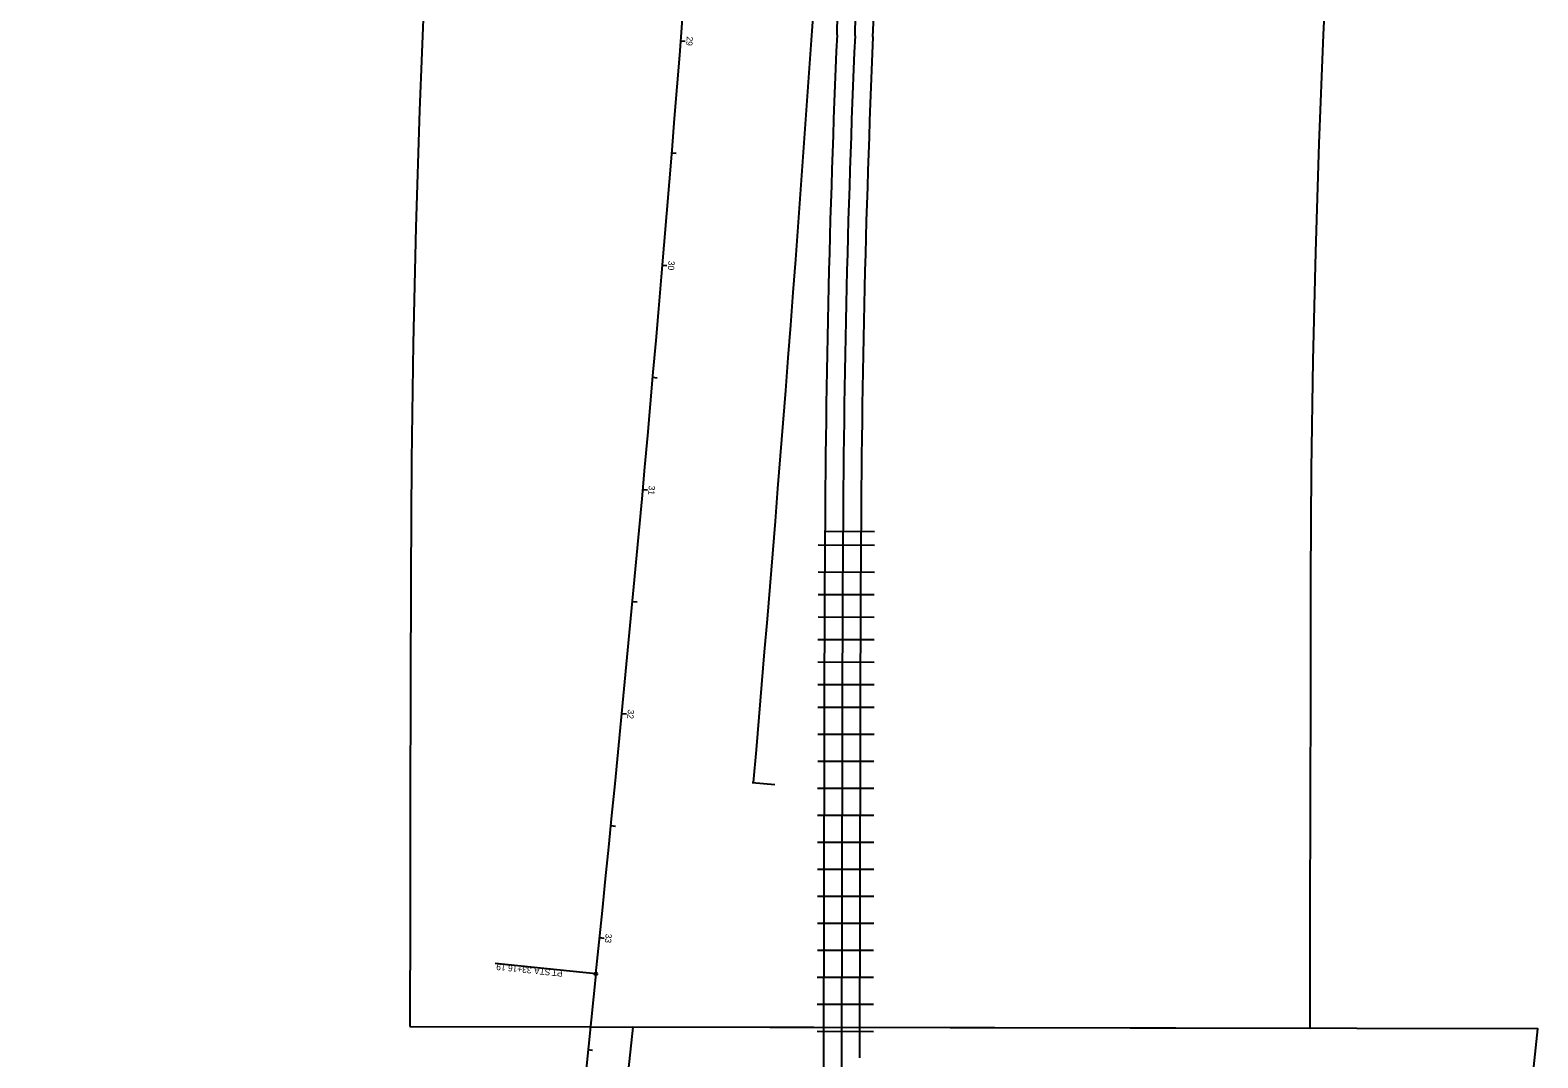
# Model space of a CAD drawing. Extents: x 172043 to 172847, y 249504 to 259737.
# Drawn here: x 172177 to 172847, y 256386 to 256843 of the extents above; entities that cross this region are included whole.
import ezdxf

# ---------------------------------------------------------------- set-up
doc = ezdxf.new("R2010")
doc.units = 0
for name, color, linetype in [('PM_X_Surveyed_Line', 7, 'Continuous'), ('PV_X_EOP', 7, 'Continuous'), ('PV_X_Shoulder', 7, 'Continuous'), ('RW_X_CL_100_Distances', 7, 'Continuous')]:
    doc.layers.add(name, color=color, linetype=linetype)

msp = doc.modelspace()

# ---------------------------------------------------------------- linework, layer by layer
at = {"layer": 'PM_X_Surveyed_Line'}
for p, q in [((172466.38, 256837.82), (172468.37, 256837.66)), ((172466.38, 256837.82), (172468.37, 256837.66)), ((172462.38, 256787.98), (172464.38, 256787.81)), ((172458.24, 256738.15), (172460.24, 256737.98)), ((172458.24, 256738.15), (172460.24, 256737.98)), ((172453.96, 256688.33), (172455.95, 256688.16)), ((172449.52, 256638.53), (172451.51, 256638.35)), ((172449.52, 256638.53), (172451.51, 256638.35)), ((172444.94, 256588.74), (172446.93, 256588.55)), ((172440.22, 256538.96), (172442.21, 256538.77)), ((172440.22, 256538.96), (172442.21, 256538.77)), ((172435.34, 256489.2), (172437.33, 256489)), ((172430.32, 256439.45), (172432.31, 256439.25)), ((172430.32, 256439.45), (172432.31, 256439.25)), ((172428.67, 256423.35), (172383.9, 256427.98)), ((172428.67, 256423.35), (172177.28, 253990.91)), ((172425.19, 256389.72), (172427.18, 256389.51))]:
    msp.add_line(p, q, dxfattribs=at)
msp.add_circle((172428.67, 256423.35), 0.6, dxfattribs=at)
msp.add_arc((155518.73, 258170.95), 17000, 354.099581, 0.195474, dxfattribs=at)
msp.add_arc((155518.73, 258170.95), 17000, 354.099581, 0.195474, dxfattribs=at)
at = {"layer": 'PV_X_EOP'}
msp.add_line((172545.97, 256386.02), (172546.38, 256601.68), dxfattribs=at)
for centre, radius, start, end in [((151025.86, 258352.49), 21551.92, 355.091243, 0.046603), ((178275.97, 256590.76), 5729.6, 177.510759, 179.890758)]:
    msp.add_arc(centre, radius, start, end, dxfattribs=at)
msp.add_open_spline([(172551.77, 256839.6), (172552.5, 256856.26), (172554.08, 256889.55), (172556.81, 256939.48), (172559.73, 256989.39), (172561.77, 257022.66), (172562.78, 257039.3)], degree=3, dxfattribs=at)
at = {"layer": 'PV_X_Shoulder'}
for points in [[(172345.99, 256399.91), (172745.99, 256399.15), (172746.09, 256449.15), (172746.18, 256499.15), (172746.28, 256549.15), (172746.37, 256599.15), (172746.66, 256647.48), (172747.36, 256695.73), (172748.49, 256743.97), (172750.04, 256792.2), (172752.01, 256840.45), (172754.37, 256888.9), (172354.92, 256909.87), (172352.41, 256858.44), (172350.3, 256806.77), (172348.64, 256755.05), (172347.43, 256703.32), (172346.68, 256651.58), (172346.37, 256599.91), (172346.28, 256549.91), (172346.18, 256499.91), (172346.09, 256449.91)], [(172393.52, 255913.31), (172791.29, 255871.19), (172796.56, 255920.91), (172801.83, 255970.63), (172807.09, 256020.35), (172812.36, 256070.07), (172817.62, 256119.8), (172822.89, 256169.52), (172828.15, 256219.24), (172833.42, 256268.96), (172838.68, 256318.68), (172847.18, 256398.96), (172445.03, 256399.72), (172440.91, 256360.81), (172435.64, 256311.09), (172430.38, 256261.36), (172425.11, 256211.64), (172419.85, 256161.92), (172414.58, 256112.2), (172409.32, 256062.48), (172404.05, 256012.75), (172398.78, 255963.03)]]:
    msp.add_lwpolyline(points, close=True, dxfattribs=at)
at = {"layer": 'RW_X_CL_100_Distances'}
for p, q in [((172530.44, 256619.92), (172552.44, 256619.81)), ((172552.41, 256613.67), (172527.41, 256613.72)), ((172552.38, 256601.66), (172527.38, 256601.73)), ((172529.97, 256386.06), (172530.38, 256601.71)), ((172537.97, 256386.04), (172538.38, 256601.7)), ((172537.97, 256386.04), (172538.38, 256601.7)), ((172552.38, 256601.67), (172538.38, 256601.7)), ((172545.97, 256386.02), (172546.38, 256601.68)), ((172552.36, 256591.67), (172527.36, 256591.72)), ((172552.34, 256581.67), (172527.34, 256581.72)), ((172552.32, 256571.67), (172527.32, 256571.72)), ((172552.3, 256561.67), (172527.3, 256561.72)), ((172552.28, 256551.67), (172527.28, 256551.72)), ((172552.26, 256541.67), (172527.26, 256541.72)), ((172552.24, 256529.67), (172527.24, 256529.72)), ((172552.22, 256517.67), (172527.22, 256517.72)), ((172498.14, 256508.36), (172508.1, 256507.51)), ((172552.19, 256505.67), (172527.19, 256505.72)), ((172552.17, 256493.67), (172527.17, 256493.72)), ((172552.15, 256481.67), (172527.15, 256481.72)), ((172552.13, 256469.67), (172527.13, 256469.72)), ((172552.1, 256457.67), (172527.1, 256457.72)), ((172552.08, 256445.67), (172527.08, 256445.72)), ((172552.06, 256433.67), (172527.06, 256433.72)), ((172552.03, 256421.67), (172527.03, 256421.72)), ((172552.01, 256409.67), (172527.01, 256409.72)), ((172551.99, 256397.61), (172526.99, 256397.76))]:
    msp.add_line(p, q, dxfattribs=at)
for centre, radius, start, end in [((178275.97, 256590.76), 5745.6, 177.509366, 179.890758), ((178275.97, 256590.76), 5737.6, 177.510062, 179.890758), ((178275.97, 256590.76), 5729.6, 177.510759, 179.890758), ((178275.97, 256590.76), 5737.6, 179.709178, 179.890758), ((170636.1, 256389.67), 1893.87, 353.95499, 359.89076), ((170636.1, 256389.67), 1901.87, 353.95499, 359.89076), ((170636.1, 256389.67), 1901.87, 353.95499, 359.89076)]:
    msp.add_arc(centre, radius, start, end, dxfattribs=at)
for points in [[(172535.79, 256840.44), (172536.52, 256857.11), (172538.1, 256890.46), (172540.84, 256940.45), (172543.76, 256990.44), (172545.81, 257023.75), (172546.82, 257040.41)], [(172543.78, 256840.02), (172544.51, 256856.68), (172546.09, 256890), (172548.83, 256939.96), (172551.74, 256989.91), (172553.79, 257023.21), (172554.8, 257039.85)], [(172551.77, 256839.6), (172552.5, 256856.26), (172554.08, 256889.55), (172556.81, 256939.48), (172559.73, 256989.39), (172561.77, 257022.66), (172562.78, 257039.3)]]:
    msp.add_open_spline(points, degree=3, dxfattribs=at)

# ---------------------------------------------------------------- texts
at = {"layer": 'PM_X_Surveyed_Line'}
for s, rotation, p in [('29', 265.50227, (172469.04, 256839.82)), ('30', 265.16524, (172460.92, 256740.16)), ('31', 264.82821, (172452.2, 256640.33)), ('32', 264.49117, (172442.91, 256540.88)), ('33', 264.15414, (172433.03, 256441.34)), ('33+16.19', 174.09958, (172400.21, 256426.25)), (' STA. ', 174.09958, (172409.61, 256425.28)), ('PT', 174.09958, (172414, 256424.83))]:
    msp.add_text(s, height=2.8, rotation=rotation, dxfattribs=at).set_placement(p)

doc.saveas('drawing.dxf')
